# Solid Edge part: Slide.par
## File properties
Author: davee
Template: Normal.par
Last saved by: davee
Revision: 4
Application: Solid Edge
Accuracy: 0.990
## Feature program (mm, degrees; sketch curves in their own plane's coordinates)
body "unnamed Body 1"
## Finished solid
Body 1: solid body, 368 faces, 833 edges, 476 vertices, 2 separate solids.
  Faces by surface: plane 158, cylinder 129, torus 28, spline 19, cone 16, sphere 8, swept 6, spun 4
  Edges by curve: line 481, circle 220, ellipse 61, intersection 29, curve on surface 21, spline 21
Bounding box of the edges (mm; curved faces can reach further): 217.316 x 250.000 x 70.002, from (-108.6581, -125, -70.0017) to (108.6581, 125, 0).
Cylindrical faces by radius (mm): R0.505 x2, R0.7575 x21, R0.808 x9, R1.01 x44, R1.111 x4, R1.515 x5, R1.6665 x2, R1.7675 x4, R2.02 x9, R2.7775 x2, R3.03 x5, R3.232 x2, R3.535 x2, R3.7575 x2, R5.05 x2, R5.2725 x2, R6.06 x4, R8.25 x4, R10.1 x1, R12.12 x2, R25.755 x1
Conical faces (half-angle, radius in mm at the cone's reference point): 1 deg R2.424 x2, 3 deg R1.515 x8, 3 deg R3.8099 x1, 3 deg R3.8205 x1, 45 deg R1.111 x2, 45 deg R2.02 x2
Toroidal faces (ring radius, tube radius in mm): R1.2625 r0.7575 x2, R2.02 r1.01 x4, R2.222 r0.808 x2, R2.2818 r0.808 x8, R2.4745 r0.7575 x2, R3.0431 r0.808 x1, R3.0538 r0.808 x1, R3.535 r2.02 x2, R5.3025 r0.7575 x2, R5.43 r1.01 x1, R5.4406 r1.01 x1, R7.07 r2.02 x2
Spherical faces by radius (mm): R1.01 x6, R1.515 x2
Planar faces by outward normal: +x 31, +y 15, +z 15, -x 15, -y 16, -z 32, oblique 34
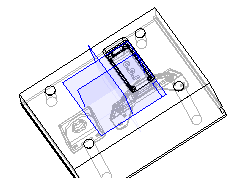
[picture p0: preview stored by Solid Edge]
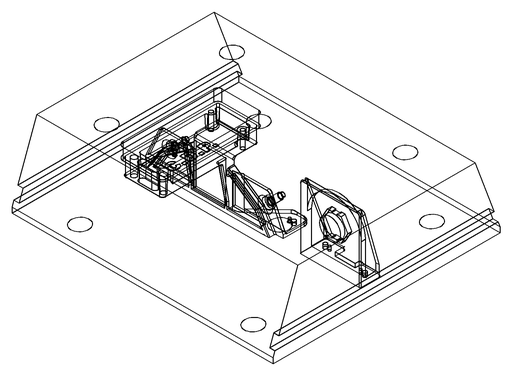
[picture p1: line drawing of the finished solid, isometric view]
